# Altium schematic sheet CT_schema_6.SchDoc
size 296 x 169 mm
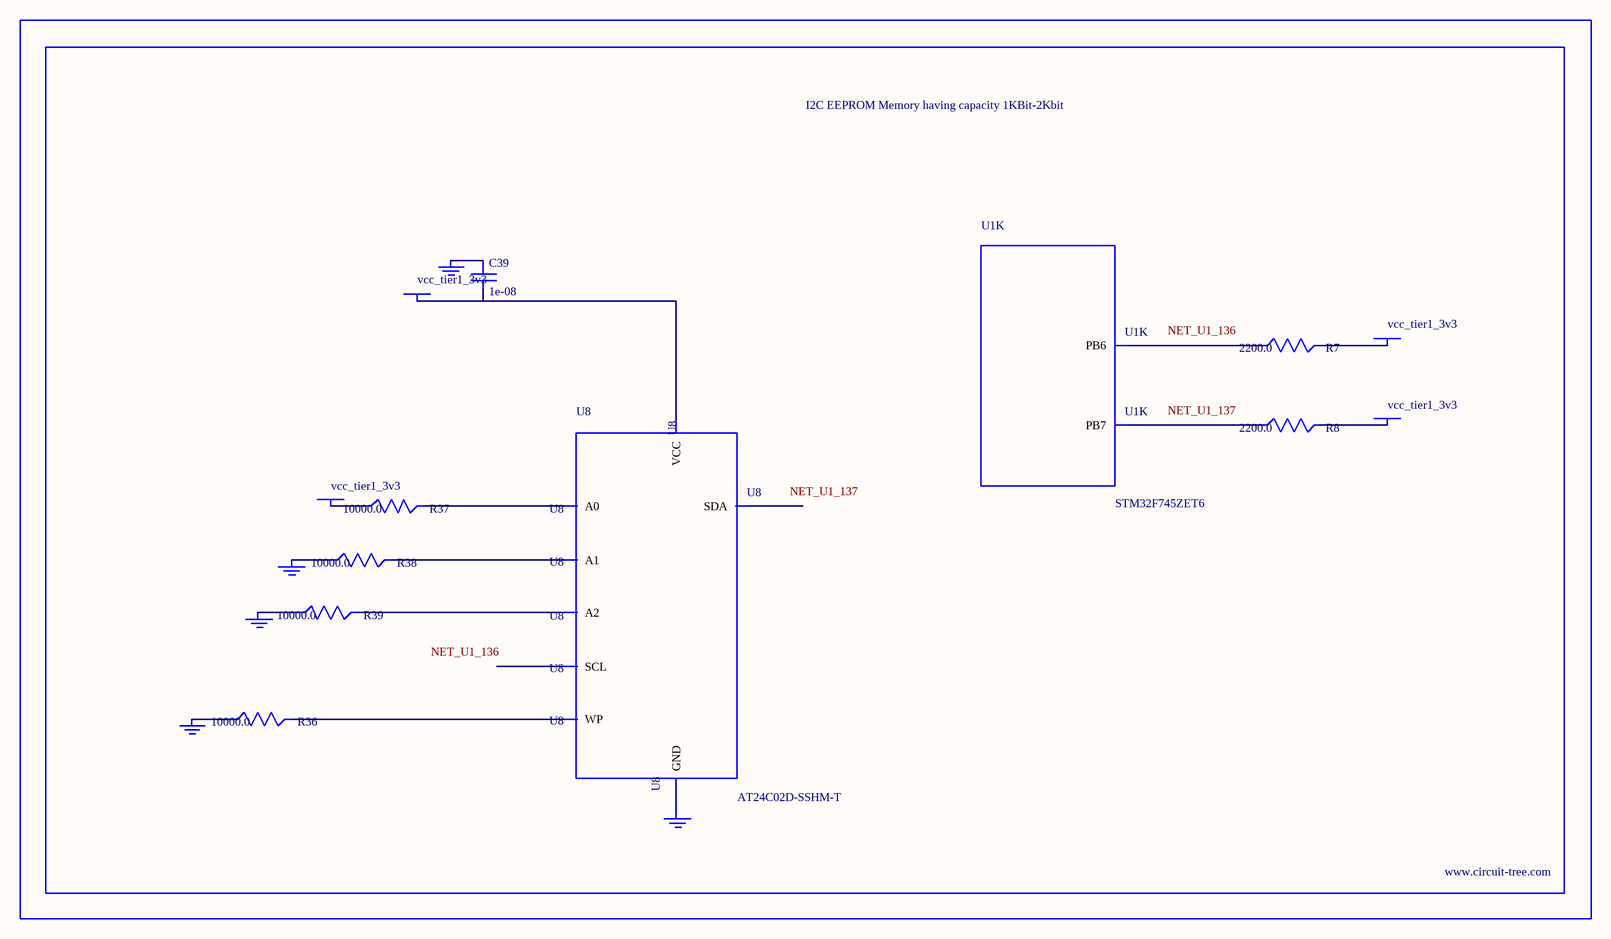
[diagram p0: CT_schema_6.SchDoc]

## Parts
BORDER5  (no value)
C39  1e-08  [C0402]
GND_INSTANCE_5_0  (no value)
GND_INSTANCE_5_1  (no value)
GND_INSTANCE_5_2  (no value)
GND_INSTANCE_5_3  (no value)
GND_INSTANCE_5_4  (no value)
POWER_INSTANCE_5_0  vcc_tier1_3v3
POWER_INSTANCE_5_1  vcc_tier1_3v3
POWER_INSTANCE_5_2  vcc_tier1_3v3
POWER_INSTANCE_5_3  vcc_tier1_3v3
R7  2200.0  [R0603]
R8  2200.0  [R0603]
R36  10000.0  [R0603]
R37  10000.0  [R0603]
R38  10000.0  [R0603]
R39  10000.0  [R0603]
U1  STM32F745ZET6  [LQFP144]  (part K of 12)
U8  AT24C02D-SSHM-T  [AT24C02D]

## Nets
NetC39_1: C39.1 GND_INSTANCE_5_3.0(GND)
NetC39_2: C39.2 POWER_INSTANCE_5_1.0(PWR) U8.8(VCC)
NetGND_INSTANCE_5_0_0: GND_INSTANCE_5_0.0(GND) R38.1
NetGND_INSTANCE_5_1_0: GND_INSTANCE_5_1.0(GND) R39.1
NetGND_INSTANCE_5_2_0: GND_INSTANCE_5_2.0(GND) R36.1
NetGND_INSTANCE_5_4_0: GND_INSTANCE_5_4.0(GND) U8.4(GND)
NetPOWER_INSTANCE_5_0_0: POWER_INSTANCE_5_0.0(PWR) R37.1
NetPOWER_INSTANCE_5_2_0: POWER_INSTANCE_5_2.0(PWR) R7.2
NetPOWER_INSTANCE_5_3_0: POWER_INSTANCE_5_3.0(PWR) R8.2
NetR7_1: R7.1 U1.136(PB6)
NetR8_1: R8.1 U1.137(PB7)
NetR36_2: R36.2 U8.7(WP)
NetR37_2: R37.2 U8.1(A0)
NetR38_2: R38.2 U8.2(A1)
NetR39_2: R39.2 U8.3(A2)

Not connected (* = marked no-connect by the designer): U8 5(SDA) 6(SCL)

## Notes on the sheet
- Labels drawn without touching a wire or pin: NET_U1_136, NET_U1_137

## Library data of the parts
BORDER5 = BORDER_PAGE5
C39 = C0402C103K3RAC
GND_INSTANCE_5_0-GND_INSTANCE_5_4 = GND
POWER_INSTANCE_5_0-POWER_INSTANCE_5_3 = PWR
R7 R8 = RC0603JR-072K2L
R36-R39 = RC0603JR-0710KL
